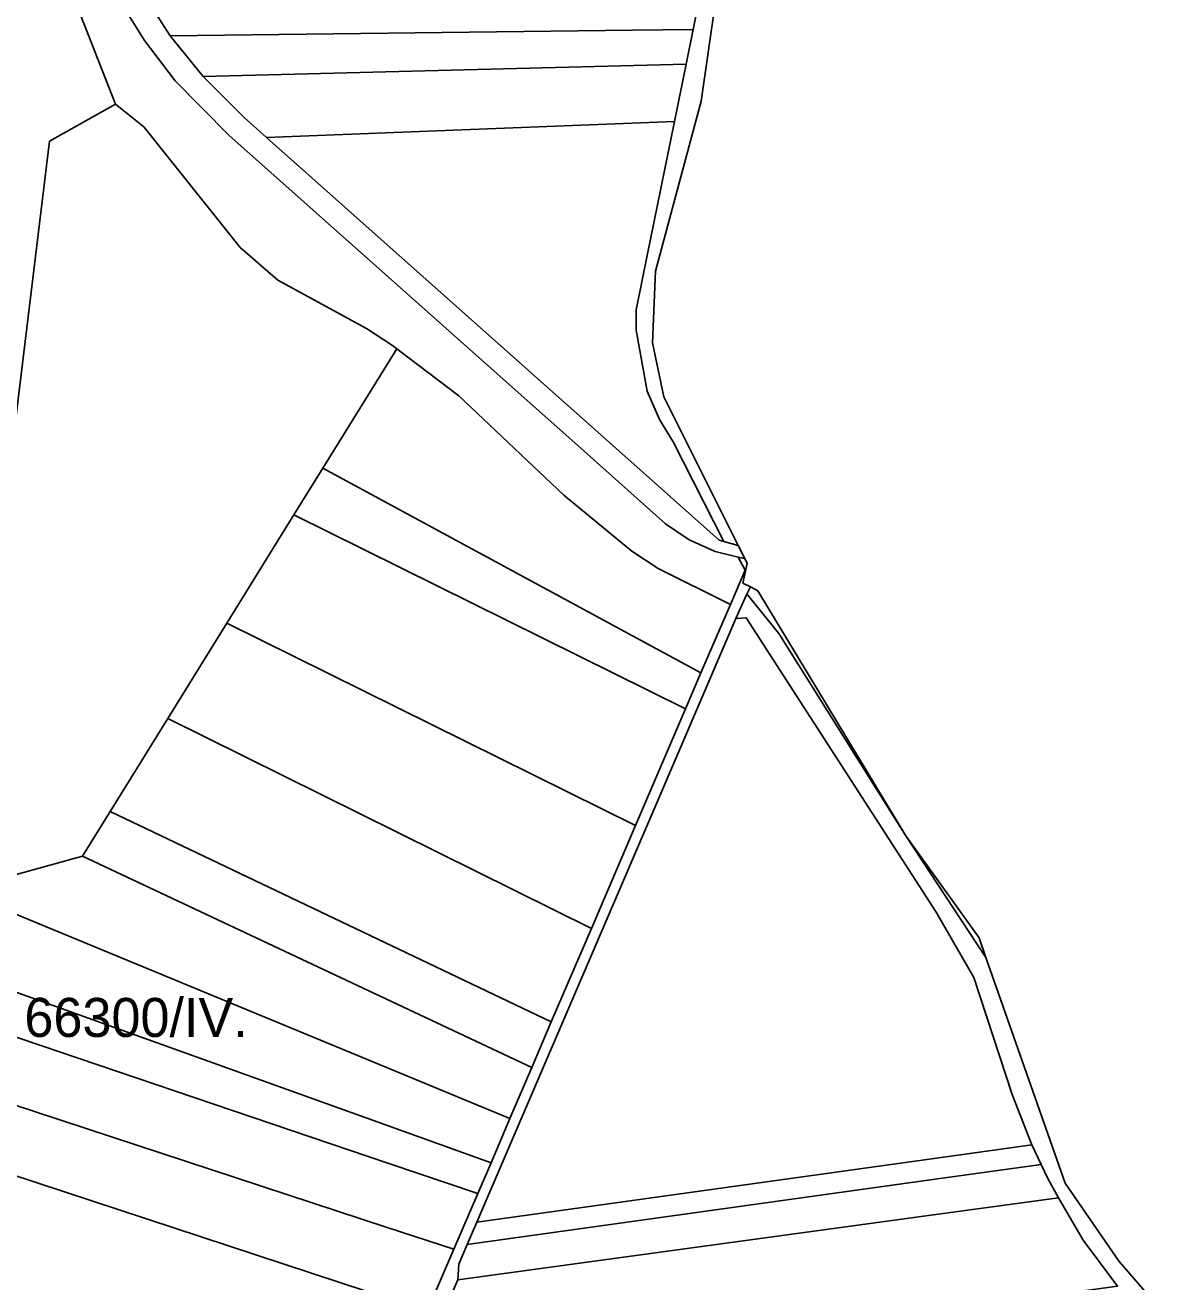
# Model space of a CAD drawing. Extents: x -521939 to -516426, y -1197857 to -1189551.
# Drawn here: x -518661.9 to -518226.4, y -1191032.2 to -1190548.8 of the extents above; entities that cross this region are included whole.
import ezdxf

# ---------------------------------------------------------------- set-up
doc = ezdxf.new("R2010")
doc.units = 0
for name, color, linetype in [('95560013', 7, 'Continuous'), ('95610013', 7, 'Continuous'), ('95630013', 7, 'Continuous'), ('95640013', 7, 'Continuous'), ('95660013', 7, 'Continuous')]:
    doc.layers.add(name, color=color, linetype=linetype)

msp = doc.modelspace()

# ---------------------------------------------------------------- linework, layer by layer
at = {"layer": '95560013'}
for points in [[(-518617.62, -1190534.74), (-518436.83, -1190530.17), (-518400.83, -1190529.26), (-518405.05, -1190550.44), (-518428.37, -1190550.73), (-518606.08, -1190552.94)], [(-518405.05, -1190550.44), (-518407.81, -1190563.81), (-518593.43, -1190568.52), (-518606.08, -1190552.94), (-518428.37, -1190550.73)], [(-518593.43, -1190568.52), (-518407.81, -1190563.81), (-518412.26, -1190585.89), (-518569.04, -1190592), (-518577.65, -1190584.34)], [(-518412.26, -1190585.89), (-518422.56, -1190636.78), (-518426.93, -1190658.23), (-518427, -1190666.17), (-518422.68, -1190689.52), (-518417.98, -1190700.45), (-518412.74, -1190709.03), (-518393.28, -1190747.38), (-518395.09, -1190746.89), (-518434.79, -1190711.54), (-518569.04, -1190592)], [(-518518.98, -1190673.29), (-518495.13, -1190691.35), (-518454.79, -1190729.54), (-518428.63, -1190751.16), (-518418.46, -1190757.75), (-518390.75, -1190771.64), (-518402.05, -1190797.95), (-518547.39, -1190719.17)], [(-518558.52, -1190737.14), (-518547.39, -1190719.17), (-518402.05, -1190797.95), (-518407.95, -1190811.74)], [(-518584.36, -1190778.86), (-518558.52, -1190737.14), (-518407.95, -1190811.74), (-518427.22, -1190856.72)], [(-518584.36, -1190778.86), (-518427.22, -1190856.72), (-518444.15, -1190896.22), (-518607.03, -1190815.46)], [(-518607.03, -1190815.46), (-518444.15, -1190896.22), (-518459.59, -1190932.22), (-518629.18, -1190851.22)], [(-518459.59, -1190932.22), (-518467.11, -1190949.79), (-518639.88, -1190868.49), (-518629.18, -1190851.22)], [(-518687.6, -1190881.68), (-518639.88, -1190868.49), (-518467.11, -1190949.79), (-518475.51, -1190969.38), (-518523.2, -1190949.66)], [(-518687.6, -1190881.68), (-518523.2, -1190949.66), (-518475.51, -1190969.38), (-518482.71, -1190986.39), (-518522.94, -1190971.94), (-518691.21, -1190911.5)], [(-518482.71, -1190986.39), (-518487.87, -1190998.24), (-518522.44, -1190986.53), (-518693.43, -1190928.61), (-518691.21, -1190911.5), (-518522.94, -1190971.94)], [(-518487.87, -1190998.24), (-518497.07, -1191019.7), (-518522.67, -1191011.28), (-518696.61, -1190954.07), (-518693.43, -1190928.61), (-518522.44, -1190986.53)], [(-518696.61, -1190954.07), (-518522.67, -1191011.28), (-518497.07, -1191019.7), (-518507.28, -1191043.48), (-518530.79, -1191035.75), (-518699.77, -1190980.19)], [(-518507.28, -1191043.48), (-518527.2, -1191089.94), (-518705.95, -1191031.23), (-518699.77, -1190980.19), (-518530.79, -1191035.75)], [(-518271.27, -1190987.05), (-518311.98, -1190992.73), (-518491.95, -1191017.84), (-518488.26, -1191009.23), (-518305.94, -1190983.82), (-518274.8, -1190979.48)], [(-518491.95, -1191017.84), (-518311.98, -1190992.73), (-518271.27, -1190987.05), (-518268.73, -1190992.48), (-518264.57, -1190999.85), (-518314.55, -1191006.68), (-518495.59, -1191031.42), (-518495.2, -1191025.44)], [(-518465.79, -1191064.52), (-518514.91, -1191071.43), (-518507.61, -1191054.38), (-518503.54, -1191049.96), (-518495.59, -1191031.42), (-518314.55, -1191006.68), (-518264.57, -1190999.85), (-518255.12, -1191016.14), (-518241.94, -1191033.87), (-518286.71, -1191040)]]:
    msp.add_lwpolyline(points, close=True, dxfattribs=at)
at = {"layer": '95610013'}
msp.add_lwpolyline([(-518418.31, -1190846.1), (-518388.71, -1190777.07), (-518384.65, -1190776.72), (-518311.69, -1190889.98), (-518297.19, -1190915.19), (-518282.39, -1190960.18), (-518274.8, -1190979.48), (-518305.94, -1190983.82), (-518488.26, -1191009.23)], close=True, dxfattribs=at)
at = {"layer": '95630013'}
for points in [[(-518661.8, -1190490.82), (-518627.12, -1190579.12), (-518652.45, -1190593.34), (-518687.6, -1190881.68), (-518691.21, -1190911.5), (-518693.43, -1190928.61), (-518696.61, -1190954.07), (-518699.77, -1190980.19), (-518705.95, -1191031.23), (-518706.78, -1191038.15)], [(-518626.27, -1190538.11), (-518616, -1190554.71), (-518604.18, -1190570.24), (-518583.63, -1190591.06), (-518445.86, -1190713.73), (-518415.66, -1190740.62), (-518406.57, -1190746.77), (-518396.54, -1190751.24), (-518387.8, -1190753.49), (-518385.06, -1190758.37), (-518390.75, -1190771.64), (-518418.46, -1190757.75), (-518428.63, -1190751.16), (-518454.79, -1190729.54), (-518495.13, -1190691.35), (-518518.98, -1190673.29), (-518520.61, -1190672.06), (-518530.66, -1190665.45), (-518564.68, -1190646.91), (-518579.17, -1190634.29), (-518616.2, -1190587.89), (-518627.12, -1190579.12), (-518661.8, -1190490.82)]]:
    msp.add_lwpolyline(points, dxfattribs=at)
for points in [[(-518380.25, -1190766.34), (-518323.33, -1190860.64), (-518372.06, -1190782.8), (-518384.04, -1190768.05), (-518384.5, -1190767.87), (-518383.03, -1190764.9)], [(-518292.5, -1190907.44), (-518323.33, -1190860.64), (-518295.13, -1190899.93)]]:
    msp.add_lwpolyline(points, close=True, dxfattribs=at)
at = {"layer": '95640013'}
for points in [[(-518396.58, -1190540.6), (-518401.98, -1190577.95), (-518419.58, -1190643.37), (-518420.69, -1190670.97), (-518416.37, -1190691.78), (-518387.76, -1190748.88), (-518393.28, -1190747.38), (-518412.74, -1190709.03), (-518417.98, -1190700.45), (-518422.68, -1190689.52), (-518427, -1190666.17), (-518426.93, -1190658.23), (-518422.56, -1190636.78), (-518412.26, -1190585.89), (-518407.81, -1190563.81), (-518405.05, -1190550.44), (-518400.83, -1190529.26)], [(-518617.62, -1190534.74), (-518606.08, -1190552.94), (-518593.43, -1190568.52), (-518577.65, -1190584.34), (-518569.04, -1190592), (-518434.79, -1190711.54), (-518395.09, -1190746.89), (-518393.28, -1190747.38), (-518387.76, -1190748.88), (-518385.21, -1190753.95), (-518385.89, -1190753.87), (-518387.8, -1190753.49), (-518396.54, -1190751.24), (-518406.57, -1190746.77), (-518415.66, -1190740.62), (-518445.86, -1190713.73), (-518583.63, -1190591.06), (-518604.18, -1190570.24), (-518616, -1190554.71), (-518626.27, -1190538.11)], [(-518507.28, -1191043.48), (-518497.07, -1191019.7), (-518487.87, -1190998.24), (-518482.71, -1190986.39), (-518475.51, -1190969.38), (-518467.11, -1190949.79), (-518459.59, -1190932.22), (-518444.15, -1190896.22), (-518427.22, -1190856.72), (-518407.95, -1190811.74), (-518402.05, -1190797.95), (-518390.75, -1190771.64), (-518385.06, -1190758.37), (-518387.8, -1190753.49), (-518385.89, -1190753.87), (-518385.21, -1190753.95), (-518384.25, -1190755.87), (-518385.9, -1190763.41), (-518383.03, -1190764.9), (-518384.5, -1190767.87), (-518388.71, -1190777.07), (-518418.31, -1190846.1), (-518488.26, -1191009.23), (-518491.95, -1191017.84), (-518495.2, -1191025.44), (-518495.59, -1191031.42), (-518503.54, -1191049.96)], [(-518241.94, -1191033.87), (-518255.12, -1191016.14), (-518264.57, -1190999.85), (-518268.73, -1190992.48), (-518271.27, -1190987.05), (-518274.8, -1190979.48), (-518282.39, -1190960.18), (-518297.19, -1190915.19), (-518311.69, -1190889.98), (-518384.65, -1190776.72), (-518388.71, -1190777.07), (-518384.5, -1190767.87), (-518384.04, -1190768.05), (-518372.06, -1190782.8), (-518323.33, -1190860.64), (-518292.5, -1190907.44), (-518262.08, -1190994.23), (-518241.31, -1191024.36), (-518226.41, -1191041.52)]]:
    msp.add_lwpolyline(points, dxfattribs=at)
msp.add_lwpolyline([(-518520.61, -1190672.06), (-518518.98, -1190673.29), (-518547.39, -1190719.17), (-518558.52, -1190737.14), (-518584.36, -1190778.86), (-518607.03, -1190815.46), (-518629.18, -1190851.22), (-518639.88, -1190868.49), (-518687.6, -1190881.68), (-518652.45, -1190593.34), (-518627.12, -1190579.12), (-518616.2, -1190587.89), (-518579.17, -1190634.29), (-518564.68, -1190646.91), (-518530.66, -1190665.45)], close=True, dxfattribs=at)
at = {"layer": '95660013'}
msp.add_lwpolyline([(-518396.58, -1190540.6), (-518401.98, -1190577.95), (-518419.58, -1190643.37), (-518420.69, -1190670.97), (-518416.37, -1190691.78), (-518387.76, -1190748.88), (-518385.21, -1190753.95), (-518384.25, -1190755.87), (-518385.9, -1190763.41), (-518383.03, -1190764.9), (-518380.25, -1190766.34), (-518323.33, -1190860.64), (-518295.13, -1190899.93), (-518292.5, -1190907.44), (-518262.08, -1190994.23), (-518241.31, -1191024.36), (-518226.41, -1191041.52)], dxfattribs=at)

# ---------------------------------------------------------------- texts
msp.add_text('66300/IV.', height=15, dxfattribs=at).set_placement((-518662.17, -1190937.99))

doc.saveas('drawing.dxf')
